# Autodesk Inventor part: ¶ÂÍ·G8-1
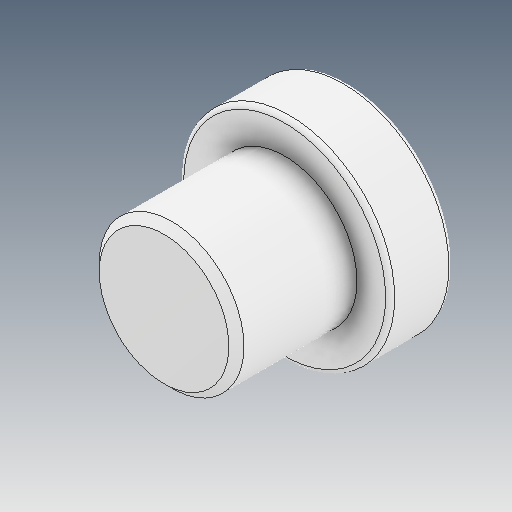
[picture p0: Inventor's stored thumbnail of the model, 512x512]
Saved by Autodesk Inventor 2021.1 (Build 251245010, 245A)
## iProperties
Created: 2021-06
Part Number: ¶ÂÍ·G8-1
Material: Ogólny
Document SubType Name: Modeling
Designer: user
Density: 1 g/cm^3
Appearance: Domyślna
Author: user
Revision Number: ÈÎºÎ
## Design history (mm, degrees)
feature "µ¹½Ç2"
node "Bryła1"
